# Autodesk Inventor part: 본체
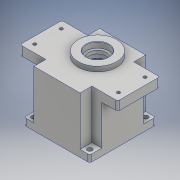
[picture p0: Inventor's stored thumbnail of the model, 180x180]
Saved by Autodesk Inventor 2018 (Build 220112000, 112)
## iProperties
Created: 2020-07
Part Number: 본체
Material: 알루미늄 6061
Document SubType Name: Modeling
Designer: admin
Density: 2.7 g/cm^3
Appearance: 알루미늄 - 평지
Mass: 917.908 g
Surface Area: 799.111 cm^2
Volume: 339.966 cm^3
Author: admin
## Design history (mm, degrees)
sketch "스케치2"
  geometry: L1 (-47, -47)-(47, -47); L2 (47, -47)-(47, 47); L3 (47, 47)-(-47, 47); L4 (-47, 47)-(-47, -47); L5 (-47, -47)-(47, 47); L6 (47, -47)-(-47, 47); 1 further point
  constraints: 12 end point, 2 midpoint, 2 parallel, 1 horizontal, 1 perpendicular
  dimensions: "d0" = 94 distance of L2.end L3.end; "d1" = 94 distance of L1.end L2.end
extrude "돌출1" new body sketch "스케치2" stored distance "d2" = 67; taper "d3" = 0 deg
sketch "스케치3"
  geometry: L1 (-70, -47)-(70, -47); L2 (70, -47)-(70, 47); L3 (70, 47)-(-70, 47); L4 (-70, 47)-(-70, -47); L5 (-70, -47)-(70, 47); L6 (70, -47)-(-70, 47); 1 further point
  constraints: 12 end point, 2 midpoint, 2 parallel, 1 horizontal, 1 perpendicular
  dimensions: "d4" = 140 distance of L2.end L3.end; "d5" = 94 distance of L1.end L2.end
extrude "돌출2" join sketch "스케치3" distance "d6" = 13; taper "d7" = 0 deg
sketch "스케치4"
  geometry: L1 (-70, -47)-(70, -47) reference; L2 (70, -47)-(70, 47) reference; L3 (70, 47)-(-70, 47) reference; L4 (-70, 47)-(-70, -47) reference; L5 (-98, 0)-(98, 0) reference; L6 (0, -65.8)-(0, 65.8) reference; L7 (-70, 47)-(-33, 47); L8 (-33, 47)-(-33, 30); L9 (-33, 30)-(-70, 30); L10 (-70, 30)-(-70, 47); L11 (70, 47)-(33, 47); L12 (70, 30)-(70, 47); L13 (33, 30)-(70, 30); L14 (33, 47)-(33, 30); L15 (-70, -47)-(-33, -47); L16 (-70, -30)-(-70, -47); L17 (-33, -30)-(-70, -30); L18 (-33, -47)-(-33, -30); L19 (33, -47)-(33, -30); L20 (33, -30)-(70, -30); L21 (70, -47)-(33, -47); L22 (70, -30)-(70, -47); 1 further point
  constraints: 32 end point, 9 symmetric about line, 2 parallel, 1 horizontal, 1 perpendicular
  dimensions: "d8" = 17 distance between parallel lines of L3 L9; "d9" = 37 distance between parallel lines of L8 L4
extrude "돌출3" cut sketch "스케치4" distance "d10" = 70; taper "d11" = 0 deg
sketch "스케치5"
  geometry: L1 (0, -65.8)-(0, 65.8) reference; L2 (-98, 0)-(98, 0) reference; C1 r 27.5 at (0, 11); 1 further point
  constraints: 1 centre point, 1 point on line
  dimensions: "d12" = 55 diameter of C1; "d13" = 11 distance from line of C1.centre L2
extrude "돌출4" join sketch "스케치5" distance "d14" = 7; taper "d15" = 0 deg
sketch "스케치6"
  geometry: L1 (0, -76.8)-(0, 54.8) reference; L2 (-98, -11)-(98, -11) reference; C1 r 16 at (0, 0); 1 further point
  constraints: 1 centre point, 1 point on line
  dimensions: "d16" = 32 diameter of C1; "d17" = 11 distance from line of C1.centre L2
extrude "돌출5" cut sketch "스케치6" distance "d18" = 8.3; taper "d19" = 0 deg
sketch "스케치7"
  geometry: L1 (-98, -11)-(98, -11) reference; L2 (0, -76.8)-(0, 54.8) reference; C1 r 12.5 at (0, 0); 1 further point
  constraints: 1 centre point, 1 point on line
  dimensions: "d20" = 25 diameter of C1; "d21" = 11 distance from line of C1.centre L1
extrude "돌출6" cut sketch "스케치7" distance "d22" = 4.7; taper "d23" = 0 deg
sketch "스케치8"
  geometry: C1 r 43 at (0, 0); 1 further point
  constraints: 1 centre point, 1 coincident
  dimensions: "d24" = 86 diameter of C1
extrude "돌출7" cut sketch "스케치8" distance "d25" = 9; taper "d26" = 0 deg
sketch "스케치9"
  geometry: C1 r 40 at (0, 0); 1 further point
  constraints: 1 centre point, 1 coincident
  dimensions: "d27" = 80 diameter of C1
extrude "돌출8" cut sketch "스케치9" distance "d28" = 62; taper "d29" = 0 deg
sketch "스케치10"
  geometry: L1 (98, 0)-(-98, 0) reference; L2 (0, -65.8)-(0, 65.8) reference; C1 r 21 at (0, 11); C2 r 15 at (0, -20); 1 further point
  constraints: 2 centre point, 2 point on line
  dimensions: "d30" = 42 diameter of C1; "d31" = 30 diameter of C2; "d32" = 11 distance from line of C1.centre L1; "d33" = 20 distance from line of C2.centre L1
extrude "돌출9" join sketch "스케치10" distance "d34" = 7; taper "d35" = 0 deg
sketch "스케치11"
  geometry: L1 (98, 0)-(-98, 0) reference; L2 (0, -65.8)-(0, 65.8) reference; C1 r 17.5 at (0, 11); 1 further point
  constraints: 1 centre point, 1 point on line
  dimensions: "d36" = 35 diameter of C1; "d37" = 11 distance from line of C1.centre L1
extrude "돌출10" cut sketch "스케치11" distance "d38" = 10; taper "d39" = 0 deg
sketch "스케치12"
  geometry: L1 (98, 0)-(-98, 0) reference; L2 (0, -65.8)-(0, 65.8) reference; C1 r 11 at (0, -20); 1 further point
  constraints: 1 centre point, 1 point on line
  dimensions: "d40" = 22 diameter of C1; "d41" = 20 distance from line of C1.centre L1
extrude "돌출11" cut sketch "스케치12" distance "d42" = 7; taper "d43" = 0 deg
sketch "스케치13"
  geometry: L1 (98, 20)-(-98, 20) reference; L2 (0, -45.8)-(0, 85.8) reference; C1 r 9.5 at (0, 0); 1 further point
  constraints: 1 centre point, 1 point on line
  dimensions: "d44" = 19 diameter of C1; "d45" = 20 distance from line of C1.centre L1
extrude "돌출12" cut sketch "스케치13" distance "d46" = 3; taper "d47" = 0 deg
sketch "스케치15"
  geometry: L1 (98, 0)-(-98, 0) reference; L2 (0, -65.8)-(0, 65.8) reference; L3 (-35.778, 3.994)-(-39.8, 3.994); L4 (-35.778, -3.994)-(-39.8, -3.994); L5 (35.778, 3.994)-(39.8, 3.994); L6 (35.778, -3.994)-(39.8, -3.994); A1 r 4 centre (-36, 0) between (-36.222, -3.994) and (-36.222, 3.994); A2 r 4 centre (36, 0) between (36.222, 3.994) and (36.222, -3.994); A3 r 40 centre (0, 0) between (-39.8, 3.994) and (-39.8, -3.994) reference; A4 r 40 centre (0, 0) between (-39.8, 3.994) and (-39.8, -3.994); A5 r 40 centre (0, 0) between (39.8, -3.994) and (39.8, 3.994); 1 further point
  constraints: 16 point on circle, 8 end point, 8 point on line, 4 centre point, 1 coincident, 1 horizontal, 1 parallel, 1 symmetric about line, 1 other
  dimensions: "d50" = 8 diameter of A1; "d51" = 8 diameter of A2; "d52" = 72 distance of A2.centre A1.centre; "d53" = 7.98764 distance between parallel lines of L6 L5; "d54" = 7.98764 distance between parallel lines of L4 L3
extrude "돌출13" join sketch "스케치15" distance "d55" = 62; taper "d56" = 0 deg
sketch "스케치17"
  geometry: L1 (98, 0)-(-98, 0) reference; L2 (0, -65.8)-(0, 65.8) reference; L3 (-60, 19)-(60, 19); L4 (60, 19)-(60, -19); L5 (60, -19)-(-60, -19); L6 (-60, -19)-(-60, 19); 5 further points
  constraints: 8 end point, 4 coincident, 2 parallel, 2 symmetric about line, 1 horizontal, 1 perpendicular
  dimensions: "d59" = 120 distance of L3.start L3.end; "d60" = 38 distance of L3.end L4.end
hole "구멍1" sketch "스케치17" at (-60, 19), (-60, -19), (60, -19), (60, 19) diameter "d61" = 4.5; stored, may be unused: countersink angle "d65" = 90 deg, drill point angle "d67" = 0 deg; dims "d62" = 6, "d63" = 10, "d64" = 5, "d66" = 13
sketch "스케치18"
  geometry: L1 (-98, 0)-(98, 0) reference; L2 (0, -65.8)-(0, 65.8) reference; L3 (40, 40)-(-40, 40); L4 (-40, 40)-(-40, -40); L5 (-40, -40)-(40, -40); L6 (40, -40)-(40, 40); 5 further points
  constraints: 8 end point, 4 coincident, 2 parallel, 2 symmetric about line, 1 horizontal, 1 perpendicular
  dimensions: "d68" = 80 distance of L3.start L3.end; "d69" = 80 distance of L5.end L3.start
hole "구멍2" sketch "스케치18" at (-40, 40), (40, 40), (-40, -40), (40, -40) diameter "d70" = 7; stored, may be unused: countersink angle "d74" = 90 deg, drill point angle "d76" = 0 deg; dims "d71" = 6, "d72" = 10, "d73" = 5, "d75" = 10
sketch "스케치19"
  geometry: L1 (98, 0)-(-98, 0) reference; L2 (0, -65.8)-(0, 65.8) reference; 5 further points
  constraints: 2 coincident
hole "구멍3" sketch "스케치19" at (-36, 0), (36, 0) diameter "d77" = 3.242; stored, may be unused: countersink angle "d81" = 90 deg, drill point angle "d83" = 118 deg; dims "d78" = 7, "d79" = 10, "d80" = 5, "d82" = 9
sketch "스케치20"
  geometry: L1 (-51, -33.5)-(145, -33.5) reference; L2 (47, 17.4)-(47, -104.4) reference; L3 (0, 0)-(94, 0) reference; 2 further points
  constraints: 1 other
  dimensions: "d84" = 0 distance from line of point (47, -40) L2; "d85" = 40 distance from line of L3 point (47, -40)
feature "엠보싱1" sketch "스케치20" dims "d0" = 94, "d1" = 94, "d86" = 0.5, "d87" = 0
fillet "모깎기1" dims "d88" = 3
fillet "모깎기2" dims "d89" = 3
fillet "모깎기3" dims "d90" = 3
fillet "모깎기4" dims "d91" = 3
chamfer "모따기1" distance "d92" = 1; stored, may be unused: second distance "d93" = 2, angle "d94" = 45 deg
fillet "모깎기5" dims "d95" = 3
chamfer "모따기2" distance "d96" = 1; stored, may be unused: second distance "d97" = 2, angle "d98" = 45 deg
chamfer "모따기3" distance "d99" = 0.8; stored, may be unused: second distance "d100" = 2, angle "d101" = 30 deg
node "솔리드1"
node "투영된 루프1"
